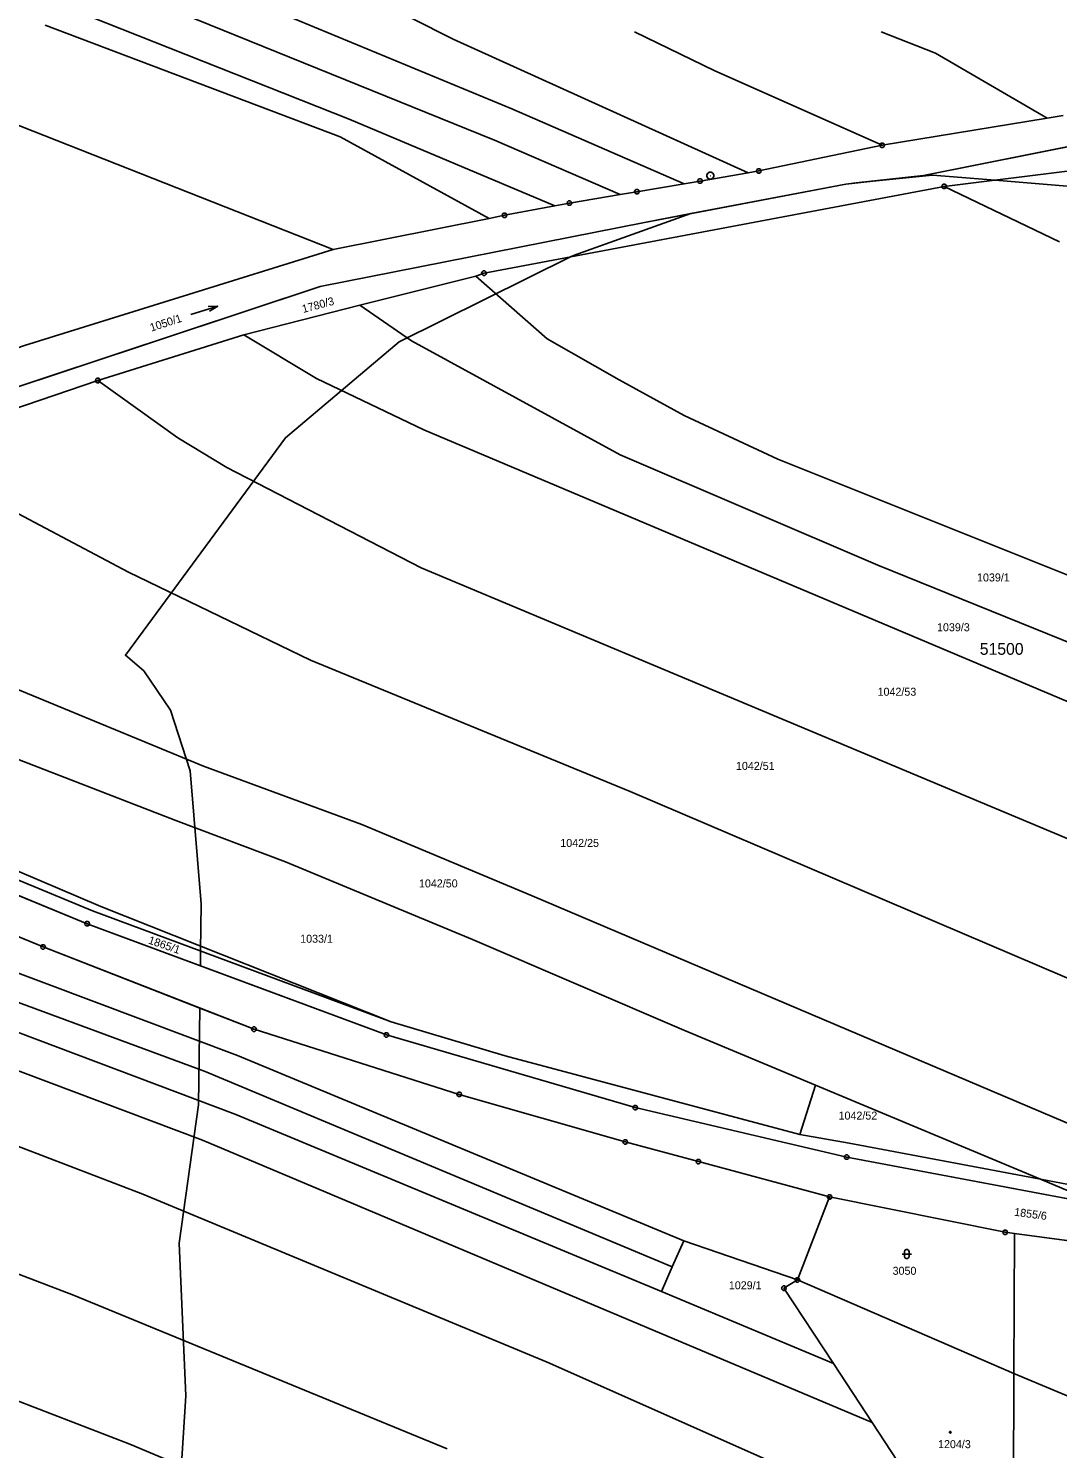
# Model space of a CAD drawing. Extents: x -777309 to -774195, y -1144706 to -1143600.
# Drawn here: x -775703 to -775484.3, y -1144501 to -1144199.3 of the extents above; entities that cross this region are included whole.
import ezdxf

# ---------------------------------------------------------------- set-up
doc = ezdxf.new("R2010")
doc.units = 0
for name, color, linetype in [('1', 7, 'Continuous'), ('11', 7, 'Continuous'), ('12', 7, 'Continuous'), ('2', 7, 'Continuous'), ('3', 7, 'Continuous'), ('5', 7, 'Continuous'), ('8', 7, 'Continuous')]:
    doc.layers.add(name, color=color, linetype=linetype)

msp = doc.modelspace()

# ---------------------------------------------------------------- linework, layer by layer
at = {"layer": '1'}
for p, q in [((-775699.57, -1144175.22), (-775600.26, -1144216.37)), ((-775702.67, -1144183.02), (-775603.93, -1144223.03)), ((-775634.82, -1144218.59), (-775714.21, -1144187.09)), ((-775635.24, -1144190.2), (-775612.76, -1144201.57)), ((-775699.39, -1144198.57), (-775636.76, -1144222.34)), ((-775574.19, -1144200), (-775557.12, -1144208.3)), ((-775521.8, -1144200), (-775510.26, -1144204.53)), ((-775550.02, -1144229.95), (-775612.76, -1144201.57)), ((-775510.26, -1144204.53), (-775486.51, -1144218.32)), ((-775557.12, -1144208.3), (-775521.56, -1144224.12)), ((-775710.57, -1144217.77), (-775638.22, -1144246.24)), ((-775634.82, -1144218.59), (-775591.14, -1144236.99)), ((-775600.26, -1144216.37), (-775563.63, -1144232.28)), ((-775486.51, -1144218.32), (-775521.56, -1144224.12)), ((-775483.1, -1144217.76), (-775486.51, -1144218.32)), ((-775512.82, -1144230.54), (-775459.3, -1144219.85)), ((-775636.76, -1144222.34), (-775605.08, -1144239.64)), ((-775577.24, -1144234.58), (-775603.93, -1144223.03)), ((-775521.56, -1144224.12), (-775547.79, -1144229.57)), ((-775550.02, -1144229.95), (-775560.27, -1144231.71)), ((-775547.79, -1144229.57), (-775550.02, -1144229.95)), ((-775529.27, -1144232.36), (-775512.82, -1144230.54)), ((-775479.98, -1144229.35), (-775508.4, -1144232.87)), ((-775508.4, -1144232.87), (-775606.17, -1144251.3)), ((-775573.68, -1144233.98), (-775577.24, -1144234.58)), ((-775563.63, -1144232.28), (-775573.68, -1144233.98)), ((-775572.06, -1144240.51), (-775529.27, -1144232.36)), ((-775560.27, -1144231.71), (-775563.63, -1144232.28)), ((-775483.88, -1144244.62), (-775508.4, -1144232.87)), ((-775591.14, -1144236.99), (-775601.8, -1144238.99)), ((-775588.03, -1144236.41), (-775591.14, -1144236.99)), ((-775577.24, -1144234.58), (-775588.03, -1144236.41)), ((-775605.08, -1144239.64), (-775638.22, -1144246.24)), ((-775601.8, -1144238.99), (-775605.08, -1144239.64)), ((-775641, -1144254.13), (-775572.06, -1144240.51)), ((-775638.22, -1144246.24), (-775703.79, -1144266.62)), ((-775607.93, -1144251.93), (-775632.59, -1144258.06)), ((-775606.17, -1144251.3), (-775607.93, -1144251.93)), ((-775607.93, -1144251.93), (-775592.73, -1144265.24)), ((-775788.13, -1144302.89), (-775641, -1144254.13)), ((-775632.59, -1144258.06), (-775657.22, -1144264.36)), ((-775621.58, -1144265.67), (-775632.59, -1144258.06)), ((-775657.22, -1144264.36), (-775688.22, -1144274.1)), ((-775657.22, -1144264.36), (-775641.76, -1144273.65)), ((-775577.27, -1144289.87), (-775621.58, -1144265.67)), ((-775592.73, -1144265.24), (-775577.44, -1144273.94)), ((-775688.22, -1144274.1), (-775726.91, -1144287.21)), ((-775671.23, -1144286.27), (-775688.22, -1144274.1)), ((-775641.76, -1144273.65), (-775618.95, -1144284.54)), ((-775577.44, -1144273.94), (-775563.67, -1144281.5)), ((-775563.67, -1144281.5), (-775543.76, -1144290.79)), ((-775618.95, -1144284.54), (-775447.05, -1144357.1)), ((-775660.82, -1144292.56), (-775671.23, -1144286.27)), ((-775522.49, -1144313.33), (-775577.27, -1144289.87)), ((-775543.76, -1144290.79), (-775411.19, -1144343.87)), ((-775660.82, -1144292.56), (-775619.55, -1144313.89)), ((-775681.69, -1144314.82), (-775705.2, -1144302.37)), ((-775681.69, -1144314.82), (-775643.03, -1144333.5)), ((-775394.06, -1144408.34), (-775619.55, -1144313.89)), ((-775419.42, -1144355.11), (-775522.49, -1144313.33)), ((-775689.36, -1144386.71), (-775837.49, -1144325.82)), ((-775838.53, -1144328.62), (-775690.5, -1144389.48)), ((-775665.78, -1144356.01), (-775720.13, -1144333.58)), ((-775575.13, -1144361.42), (-775643.03, -1144333.5)), ((-775792.62, -1144341.02), (-775687.59, -1144385.81)), ((-775671.65, -1144367.58), (-775726.63, -1144346.28)), ((-775665.78, -1144356.01), (-775632.16, -1144368.38)), ((-775699.86, -1144394.42), (-775786.82, -1144358.72)), ((-775397.11, -1144437.29), (-775575.13, -1144361.42)), ((-775671.65, -1144367.58), (-775648.34, -1144376.34)), ((-775595.92, -1144383.54), (-775632.16, -1144368.38)), ((-775648.34, -1144376.34), (-775608.65, -1144392.86)), ((-775595.92, -1144383.54), (-775436.47, -1144451.33)), ((-775678.64, -1144446.95), (-775834.11, -1144387.34)), ((-775737.35, -1144387.92), (-775658.54, -1144417.49)), ((-775625.87, -1144410.3), (-775689.36, -1144386.71)), ((-775687.59, -1144385.81), (-775625.87, -1144410.3)), ((-775665.4, -1144420.9), (-775746.52, -1144390.85)), ((-775690.5, -1144389.48), (-775626.91, -1144413.11)), ((-775781.01, -1144392.22), (-775665.99, -1144435.45)), ((-775658.94, -1144429.99), (-775756.48, -1144393.32)), ((-775608.65, -1144392.86), (-775563.71, -1144412.12)), ((-775699.86, -1144394.42), (-775655.04, -1144411.89)), ((-775655.04, -1144411.89), (-775611.43, -1144425.73)), ((-775601.66, -1144417.55), (-775625.87, -1144410.3)), ((-775563.71, -1144412.12), (-775535.75, -1144423.8)), ((-775626.91, -1144413.11), (-775574.03, -1144428.55)), ((-775658.54, -1144417.49), (-775563.73, -1144456.87)), ((-775539.06, -1144434.24), (-775601.66, -1144417.55)), ((-775566.16, -1144462.36), (-775665.4, -1144420.9)), ((-775539.06, -1144434.24), (-775535.75, -1144423.8)), ((-775535.75, -1144423.8), (-775487.96, -1144443.76)), ((-775807.58, -1144424.84), (-775693.38, -1144468.4)), ((-775576.16, -1144435.84), (-775611.43, -1144425.73)), ((-775658.94, -1144429.99), (-775568.49, -1144467.61)), ((-775574.03, -1144428.55), (-775529.11, -1144439.07)), ((-775523.71, -1144495.46), (-775665.99, -1144435.45)), ((-775560.62, -1144440.02), (-775576.16, -1144435.84)), ((-775528.56, -1144436.11), (-775539.06, -1144434.24)), ((-775487.96, -1144443.76), (-775528.56, -1144436.11)), ((-775529.11, -1144439.07), (-775474.88, -1144449.28)), ((-775532.74, -1144447.53), (-775560.62, -1144440.02)), ((-775487.96, -1144443.76), (-775474.88, -1144449.28)), ((-775474.32, -1144446.33), (-775487.96, -1144443.76)), ((-775678.64, -1144446.95), (-775592.79, -1144482.59)), ((-775532.74, -1144447.53), (-775539.58, -1144465.16)), ((-775495.43, -1144455.04), (-775532.74, -1144447.53)), ((-775563.73, -1144456.87), (-775566.16, -1144462.36)), ((-775563.73, -1144456.87), (-775539.58, -1144465.16)), ((-775493.48, -1144455.3), (-775495.43, -1144455.04)), ((-775493.58, -1144485.06), (-775493.48, -1144455.3)), ((-775493.48, -1144455.3), (-775445.43, -1144461.73)), ((-775566.16, -1144462.36), (-775568.49, -1144467.61)), ((-775542.44, -1144466.92), (-775539.58, -1144465.16)), ((-775539.58, -1144465.16), (-775493.58, -1144485.06)), ((-775693.38, -1144468.4), (-775614.03, -1144501.05)), ((-775568.49, -1144467.61), (-775531.94, -1144482.93)), ((-775531.94, -1144482.93), (-775542.44, -1144466.92)), ((-775736.49, -1144478.85), (-775681.45, -1144500.07)), ((-775507.21, -1144520.6), (-775592.79, -1144482.59)), ((-775523.71, -1144495.46), (-775531.94, -1144482.93)), ((-775493.58, -1144486.33), (-775493.7, -1144510.05)), ((-775493.58, -1144485.06), (-775493.58, -1144486.33)), ((-775493.58, -1144485.06), (-775456.54, -1144500.61)), ((-775507.21, -1144520.6), (-775523.71, -1144495.46)), ((-775607.18, -1144531.04), (-775681.45, -1144500.07))]:
    msp.add_line(p, q, dxfattribs=at)
at = {"layer": '11'}
for points in [[(-775483.1, -1144217.76), (-775486.51, -1144218.32), (-775521.56, -1144224.12), (-775547.79, -1144229.57), (-775550.02, -1144229.95), (-775560.27, -1144231.71), (-775563.63, -1144232.28), (-775573.68, -1144233.98), (-775577.24, -1144234.58), (-775588.03, -1144236.41), (-775591.14, -1144236.99), (-775601.8, -1144238.99), (-775605.08, -1144239.64), (-775638.22, -1144246.24), (-775703.79, -1144266.62), (-775741.65, -1144279.72), (-775784.72, -1144293.94), (-775787.46, -1144294.84), (-775863.23, -1144318.85)], [(-775527.1, -1144232.12), (-775512.82, -1144230.54), (-775459.3, -1144219.85)], [(-775527.1, -1144232.12), (-775510.91, -1144230.43), (-775497.58, -1144231.53), (-775475.5, -1144233.35), (-775431.56, -1144243.14), (-775401.57, -1144257.3), (-775393.93, -1144261.61), (-775347.01, -1144288.12), (-775319.73, -1144319.98), (-775311.81, -1144333.34), (-775308.24, -1144339.37)], [(-775562.23, -1144238.64), (-775529.27, -1144232.36), (-775527.1, -1144232.12)], [(-775562.23, -1144238.64), (-775572.06, -1144240.51), (-775641, -1144254.13), (-775788.13, -1144302.89), (-775847.52, -1144320.58), (-775854.19, -1144322.57), (-775848.16, -1144325.04), (-775838.53, -1144328.62), (-775690.5, -1144389.48), (-775666.42, -1144398.43)], [(-775666.42, -1144398.43), (-775666.38, -1144395.25), (-775666.24, -1144385.27), (-775668.61, -1144356.98), (-775672.76, -1144344.11), (-775678.43, -1144335.77), (-775682.38, -1144332.44), (-775648.36, -1144286.25), (-775624.2, -1144265.84), (-775587.78, -1144247.83), (-775587.13, -1144247.51), (-775562.23, -1144238.64)], [(-776064.26, -1144245.03), (-775971.84, -1144282.92), (-775964.09, -1144286.42), (-775962.59, -1144286.8), (-775961.16, -1144287.17), (-775959.71, -1144287.76), (-775879.1, -1144320.81), (-775872.73, -1144323.39), (-775865.63, -1144326.37), (-775860.54, -1144328.51), (-775858.65, -1144329.3), (-775851.34, -1144332.37), (-775839.31, -1144337.25), (-775824.31, -1144343.39), (-775786.82, -1144358.72), (-775699.86, -1144394.42), (-775666.55, -1144407.41)], [(-775666.42, -1144398.43), (-775626.91, -1144413.11), (-775574.03, -1144428.55), (-775529.11, -1144439.07), (-775474.88, -1144449.28), (-775426.17, -1144455.72), (-775417.93, -1144456.81), (-775377.95, -1144459.1), (-775351.35, -1144460.68), (-775341.64, -1144460.83), (-775337.71, -1144460.89), (-775301.48, -1144461.27), (-775254.16, -1144459.9), (-775170.99, -1144453.66), (-775164.13, -1144452.88)], [(-775666.55, -1144407.41), (-775666.83, -1144427.98), (-775670.98, -1144457.34), (-775669.53, -1144489.78), (-775670.86, -1144510.96), (-775672.62, -1144526.1), (-775678.04, -1144552.51), (-775691.93, -1144600)], [(-775666.55, -1144407.41), (-775655.04, -1144411.89), (-775611.43, -1144425.73), (-775576.16, -1144435.84), (-775560.62, -1144440.02), (-775532.74, -1144447.53), (-775495.43, -1144455.04), (-775493.48, -1144455.3), (-775445.43, -1144461.73)]]:
    msp.add_lwpolyline(points, dxfattribs=at)
at = {"layer": '12'}
for p, q in [((-775542.44, -1144466.92), (-775539.58, -1144465.16)), ((-775539.58, -1144465.16), (-775493.58, -1144485.06)), ((-775531.94, -1144482.93), (-775542.44, -1144466.92)), ((-775523.71, -1144495.46), (-775531.94, -1144482.93)), ((-775493.58, -1144486.33), (-775493.7, -1144510.05)), ((-775493.58, -1144485.06), (-775493.58, -1144486.33)), ((-775507.21, -1144520.6), (-775523.71, -1144495.46))]:
    msp.add_line(p, q, dxfattribs=at)
at = {"layer": '3'}
msp.add_line((-775668.45, -1144260.07), (-775662.73, -1144258.27), dxfattribs=at)
for points in [[(-775664.78, -1144258.39), (-775662.73, -1144258.27), (-775664.49, -1144259.35)], [(-775517.36, -1144459.65), (-775516.09, -1144459.65), (-775515.36, -1144459.65)]]:
    msp.add_lwpolyline(points, dxfattribs=at)
msp.add_lwpolyline([(-775516.86, -1144459.15), (-775516.76, -1144458.86), (-775516.51, -1144458.68), (-775516.2, -1144458.68), (-775515.95, -1144458.86), (-775515.85, -1144459.15), (-775515.85, -1144460.15), (-775515.95, -1144460.44), (-775516.2, -1144460.62), (-775516.51, -1144460.62), (-775516.76, -1144460.44), (-775516.86, -1144460.15)], close=True, dxfattribs=at)
at = {"layer": '5'}
msp.add_lwpolyline([(-775507.11, -1144497.35), (-775507.01, -1144497.37), (-775506.96, -1144497.46), (-775506.94, -1144497.52), (-775506.96, -1144497.61), (-775507.04, -1144497.68), (-775507.11, -1144497.69), (-775507.2, -1144497.66), (-775507.26, -1144497.6), (-775507.28, -1144497.52), (-775507.26, -1144497.43), (-775507.18, -1144497.36)], close=True, dxfattribs=at)
at = {"layer": '8'}
for p, q in [((-775521.68, -1144224.12), (-775521.44, -1144224.12)), ((-775558.12, -1144230.58), (-775558.02, -1144230.58)), ((-775547.91, -1144229.57), (-775547.67, -1144229.57)), ((-775573.8, -1144233.98), (-775573.56, -1144233.98)), ((-775560.39, -1144231.71), (-775560.15, -1144231.71)), ((-775508.52, -1144232.87), (-775508.28, -1144232.87)), ((-775588.15, -1144236.41), (-775587.91, -1144236.41)), ((-775601.92, -1144238.99), (-775601.68, -1144238.99)), ((-775606.29, -1144251.3), (-775606.05, -1144251.3)), ((-775688.34, -1144274.1), (-775688.1, -1144274.1)), ((-775690.62, -1144389.48), (-775690.38, -1144389.48)), ((-775699.98, -1144394.42), (-775699.74, -1144394.42)), ((-775655.16, -1144411.89), (-775654.92, -1144411.89)), ((-775627.03, -1144413.11), (-775626.79, -1144413.11)), ((-775611.55, -1144425.73), (-775611.31, -1144425.73)), ((-775574.15, -1144428.55), (-775573.91, -1144428.55)), ((-775576.28, -1144435.84), (-775576.04, -1144435.84)), ((-775529.23, -1144439.07), (-775528.99, -1144439.07)), ((-775560.74, -1144440.02), (-775560.5, -1144440.02)), ((-775532.86, -1144447.53), (-775532.62, -1144447.53)), ((-775495.55, -1144455.04), (-775495.31, -1144455.04)), ((-775539.7, -1144465.16), (-775539.46, -1144465.16)), ((-775542.56, -1144466.92), (-775542.32, -1144466.92))]:
    msp.add_line(p, q, dxfattribs=at)
for points in [[(-775521.41, -1144223.64), (-775521.16, -1144223.82), (-775521.06, -1144224.11), (-775521.16, -1144224.4), (-775521.41, -1144224.58), (-775521.72, -1144224.58), (-775521.97, -1144224.4), (-775522.07, -1144224.11), (-775521.97, -1144223.82), (-775521.72, -1144223.64)], [(-775560.12, -1144231.23), (-775559.87, -1144231.41), (-775559.77, -1144231.7), (-775559.87, -1144231.99), (-775560.12, -1144232.17), (-775560.43, -1144232.17), (-775560.68, -1144231.99), (-775560.78, -1144231.7), (-775560.68, -1144231.41), (-775560.43, -1144231.23)], [(-775557.88, -1144229.86), (-775557.54, -1144230.05), (-775557.35, -1144230.39), (-775557.35, -1144230.78), (-775557.54, -1144231.12), (-775557.88, -1144231.31), (-775558.27, -1144231.31), (-775558.61, -1144231.12), (-775558.8, -1144230.78), (-775558.8, -1144230.39), (-775558.61, -1144230.05), (-775558.27, -1144229.86)], [(-775547.64, -1144229.09), (-775547.39, -1144229.27), (-775547.29, -1144229.56), (-775547.39, -1144229.85), (-775547.64, -1144230.03), (-775547.95, -1144230.03), (-775548.2, -1144229.85), (-775548.3, -1144229.56), (-775548.2, -1144229.27), (-775547.95, -1144229.09)], [(-775573.53, -1144233.5), (-775573.28, -1144233.68), (-775573.18, -1144233.97), (-775573.28, -1144234.26), (-775573.53, -1144234.44), (-775573.84, -1144234.44), (-775574.09, -1144234.26), (-775574.19, -1144233.97), (-775574.09, -1144233.68), (-775573.84, -1144233.5)], [(-775508.25, -1144232.39), (-775508, -1144232.57), (-775507.9, -1144232.86), (-775508, -1144233.15), (-775508.25, -1144233.33), (-775508.56, -1144233.33), (-775508.81, -1144233.15), (-775508.91, -1144232.86), (-775508.81, -1144232.57), (-775508.56, -1144232.39)], [(-775587.88, -1144235.93), (-775587.63, -1144236.11), (-775587.53, -1144236.4), (-775587.63, -1144236.69), (-775587.88, -1144236.87), (-775588.19, -1144236.87), (-775588.44, -1144236.69), (-775588.54, -1144236.4), (-775588.44, -1144236.11), (-775588.19, -1144235.93)], [(-775601.65, -1144238.51), (-775601.4, -1144238.69), (-775601.3, -1144238.98), (-775601.4, -1144239.27), (-775601.65, -1144239.45), (-775601.96, -1144239.45), (-775602.21, -1144239.27), (-775602.31, -1144238.98), (-775602.21, -1144238.69), (-775601.96, -1144238.51)], [(-775606.02, -1144250.82), (-775605.77, -1144251), (-775605.67, -1144251.29), (-775605.77, -1144251.58), (-775606.02, -1144251.76), (-775606.33, -1144251.76), (-775606.58, -1144251.58), (-775606.68, -1144251.29), (-775606.58, -1144251), (-775606.33, -1144250.82)], [(-775688.07, -1144273.62), (-775687.82, -1144273.8), (-775687.72, -1144274.09), (-775687.82, -1144274.38), (-775688.07, -1144274.56), (-775688.38, -1144274.56), (-775688.63, -1144274.38), (-775688.73, -1144274.09), (-775688.63, -1144273.8), (-775688.38, -1144273.62)], [(-775690.35, -1144389), (-775690.1, -1144389.18), (-775690, -1144389.47), (-775690.1, -1144389.76), (-775690.35, -1144389.94), (-775690.66, -1144389.94), (-775690.91, -1144389.76), (-775691.01, -1144389.47), (-775690.91, -1144389.18), (-775690.66, -1144389)], [(-775699.71, -1144393.94), (-775699.46, -1144394.12), (-775699.36, -1144394.41), (-775699.46, -1144394.7), (-775699.71, -1144394.88), (-775700.02, -1144394.88), (-775700.27, -1144394.7), (-775700.37, -1144394.41), (-775700.27, -1144394.12), (-775700.02, -1144393.94)], [(-775654.89, -1144411.41), (-775654.64, -1144411.59), (-775654.54, -1144411.88), (-775654.64, -1144412.17), (-775654.89, -1144412.35), (-775655.2, -1144412.35), (-775655.45, -1144412.17), (-775655.55, -1144411.88), (-775655.45, -1144411.59), (-775655.2, -1144411.41)], [(-775626.76, -1144412.63), (-775626.51, -1144412.81), (-775626.41, -1144413.1), (-775626.51, -1144413.39), (-775626.76, -1144413.57), (-775627.07, -1144413.57), (-775627.32, -1144413.39), (-775627.42, -1144413.1), (-775627.32, -1144412.81), (-775627.07, -1144412.63)], [(-775611.28, -1144425.25), (-775611.03, -1144425.43), (-775610.93, -1144425.72), (-775611.03, -1144426.01), (-775611.28, -1144426.19), (-775611.59, -1144426.19), (-775611.84, -1144426.01), (-775611.94, -1144425.72), (-775611.84, -1144425.43), (-775611.59, -1144425.25)], [(-775573.88, -1144428.07), (-775573.63, -1144428.25), (-775573.53, -1144428.54), (-775573.63, -1144428.83), (-775573.88, -1144429.01), (-775574.19, -1144429.01), (-775574.44, -1144428.83), (-775574.54, -1144428.54), (-775574.44, -1144428.25), (-775574.19, -1144428.07)], [(-775576.01, -1144435.36), (-775575.76, -1144435.54), (-775575.66, -1144435.83), (-775575.76, -1144436.12), (-775576.01, -1144436.3), (-775576.32, -1144436.3), (-775576.57, -1144436.12), (-775576.67, -1144435.83), (-775576.57, -1144435.54), (-775576.32, -1144435.36)], [(-775560.47, -1144439.54), (-775560.22, -1144439.72), (-775560.12, -1144440.01), (-775560.22, -1144440.3), (-775560.47, -1144440.48), (-775560.78, -1144440.48), (-775561.03, -1144440.3), (-775561.13, -1144440.01), (-775561.03, -1144439.72), (-775560.78, -1144439.54)], [(-775528.96, -1144438.59), (-775528.71, -1144438.77), (-775528.61, -1144439.06), (-775528.71, -1144439.35), (-775528.96, -1144439.53), (-775529.27, -1144439.53), (-775529.52, -1144439.35), (-775529.62, -1144439.06), (-775529.52, -1144438.77), (-775529.27, -1144438.59)], [(-775532.59, -1144447.05), (-775532.34, -1144447.23), (-775532.24, -1144447.52), (-775532.34, -1144447.81), (-775532.59, -1144447.99), (-775532.9, -1144447.99), (-775533.15, -1144447.81), (-775533.25, -1144447.52), (-775533.15, -1144447.23), (-775532.9, -1144447.05)], [(-775495.28, -1144454.56), (-775495.03, -1144454.74), (-775494.93, -1144455.03), (-775495.03, -1144455.32), (-775495.28, -1144455.5), (-775495.59, -1144455.5), (-775495.84, -1144455.32), (-775495.94, -1144455.03), (-775495.84, -1144454.74), (-775495.59, -1144454.56)], [(-775542.29, -1144466.44), (-775542.04, -1144466.62), (-775541.94, -1144466.91), (-775542.04, -1144467.2), (-775542.29, -1144467.38), (-775542.6, -1144467.38), (-775542.85, -1144467.2), (-775542.95, -1144466.91), (-775542.85, -1144466.62), (-775542.6, -1144466.44)], [(-775539.43, -1144464.68), (-775539.18, -1144464.86), (-775539.08, -1144465.15), (-775539.18, -1144465.44), (-775539.43, -1144465.62), (-775539.74, -1144465.62), (-775539.99, -1144465.44), (-775540.09, -1144465.15), (-775539.99, -1144464.86), (-775539.74, -1144464.68)]]:
    msp.add_lwpolyline(points, close=True, dxfattribs=at)

# ---------------------------------------------------------------- texts
at = {"layer": '11'}
msp.add_text('51500', height=2.5, dxfattribs=at).set_placement((-775500.83, -1144332.35))
at = {"layer": '2'}
for s, rotation, p in [('1780/3', 15.0115, (-775644.59, -1144259.75)), ('1050/1', 18.0482, (-775676.85, -1144263.71)), ('1865/1', 341.0245, (-775677.65, -1144393.65)), ('1855/6', 352.1399, (-775493.59, -1144451.49))]:
    msp.add_text(s, height=1.7, rotation=rotation, dxfattribs=at).set_placement(p)
for s, p in [('1039/1', (-775501.42, -1144316.77)), ('1039/3', (-775509.92, -1144327.35)), ('1042/53', (-775522.55, -1144341.05)), ('1042/51', (-775552.64, -1144356.8)), ('1042/25', (-775589.96, -1144373.17)), ('1042/50', (-775619.99, -1144381.77)), ('1033/1', (-775645.23, -1144393.52)), ('1042/52', (-775530.84, -1144431.09)), ('3050', (-775519.36, -1144464.06)), ('1029/1', (-775554.15, -1144467.14)), ('1204/3', (-775509.7, -1144500.89))]:
    msp.add_text(s, height=1.7, dxfattribs=at).set_placement(p)

doc.saveas('drawing.dxf')
